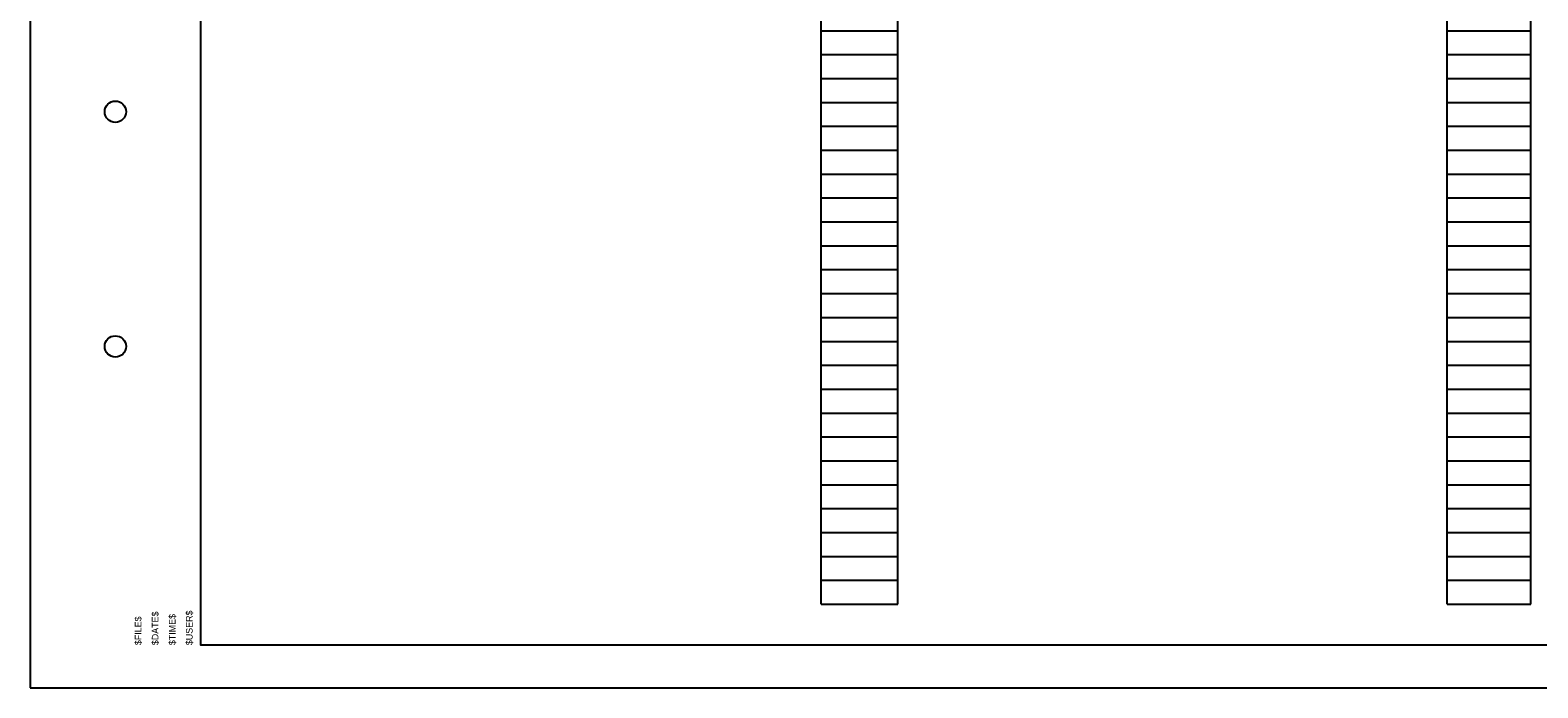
# Model space of a CAD drawing. Extents: x -16 to 102, y -13 to 9.
# Drawn here: x 22.37 to 40.05, y -12.91 to -5.2 of the extents above; entities that cross this region are included whole.
import ezdxf

# ---------------------------------------------------------------- set-up
doc = ezdxf.new("R2010")
doc.units = 0
for name, color, linetype in [('SH_Border', 7, 'Continuous'), ('SH_Cut_Line', 7, 'Continuous'), ('SH_Data', 7, 'Continuous'), ('TX_P_Misc', 7, 'Continuous')]:
    doc.layers.add(name, color=color, linetype=linetype)

msp = doc.modelspace()

# ---------------------------------------------------------------- linework, layer by layer
at = {"layer": 'SH_Border'}
msp.add_lwpolyline([(24.368, 8.593), (55.868, 8.593), (55.868, -12.407), (24.368, -12.407)], close=True, dxfattribs=at)
for centre in [(23.368, -6.157), (23.368, -8.907)]:
    msp.add_circle(centre, 0.125, dxfattribs=at)
at = {"layer": 'SH_Cut_Line'}
msp.add_lwpolyline([(22.368, -12.907), (56.368, -12.907), (56.368, 9.093), (22.368, 9.093)], close=True, dxfattribs=at)
at = {"layer": 'SH_Data'}
for p, q in [((31.642, -11.927), (31.642, 8.233)), ((32.542, -11.927), (32.542, 8.233)), ((38.982, -11.927), (38.982, 8.233)), ((39.962, -11.927), (39.962, 8.233)), ((31.642, -5.207), (32.542, -5.207)), ((38.982, -5.207), (39.962, -5.207)), ((31.642, -5.487), (32.542, -5.487)), ((38.982, -5.487), (39.962, -5.487)), ((31.642, -5.767), (32.542, -5.767)), ((38.982, -5.767), (39.962, -5.767)), ((31.642, -6.047), (32.542, -6.047)), ((38.982, -6.047), (39.962, -6.047)), ((31.642, -6.327), (32.542, -6.327)), ((38.982, -6.327), (39.962, -6.327)), ((31.642, -6.607), (32.542, -6.607)), ((38.982, -6.607), (39.962, -6.607)), ((31.642, -6.887), (32.542, -6.887)), ((38.982, -6.887), (39.962, -6.887)), ((31.642, -7.167), (32.542, -7.167)), ((38.982, -7.167), (39.962, -7.167)), ((31.642, -7.447), (32.542, -7.447)), ((38.982, -7.447), (39.962, -7.447)), ((31.642, -7.727), (32.542, -7.727)), ((38.982, -7.727), (39.962, -7.727)), ((31.642, -8.007), (32.542, -8.007)), ((38.982, -8.007), (39.962, -8.007)), ((31.642, -8.287), (32.542, -8.287)), ((38.982, -8.287), (39.962, -8.287)), ((31.642, -8.567), (32.542, -8.567)), ((38.982, -8.567), (39.962, -8.567)), ((31.642, -8.847), (32.542, -8.847)), ((38.982, -8.847), (39.962, -8.847)), ((31.642, -9.127), (32.542, -9.127)), ((38.982, -9.127), (39.962, -9.127)), ((31.642, -9.407), (32.542, -9.407)), ((38.982, -9.407), (39.962, -9.407)), ((31.642, -9.687), (32.542, -9.687)), ((38.982, -9.687), (39.962, -9.687)), ((31.642, -9.967), (32.542, -9.967)), ((38.982, -9.967), (39.962, -9.967)), ((31.642, -10.247), (32.542, -10.247)), ((38.982, -10.247), (39.962, -10.247)), ((31.642, -10.527), (32.542, -10.527)), ((38.982, -10.527), (39.962, -10.527)), ((31.642, -10.807), (32.542, -10.807)), ((38.982, -10.807), (39.962, -10.807)), ((31.642, -11.087), (32.542, -11.087)), ((38.982, -11.087), (39.962, -11.087)), ((31.642, -11.367), (32.542, -11.367)), ((38.982, -11.367), (39.962, -11.367)), ((31.642, -11.647), (32.542, -11.647)), ((38.982, -11.647), (39.962, -11.647)), ((31.642, -11.927), (32.542, -11.927)), ((38.982, -11.927), (39.962, -11.927)), ((29.642, -12.907), (29.642, -12.907))]:
    msp.add_line(p, q, dxfattribs=at)

# ---------------------------------------------------------------- texts
at = {"layer": 'TX_P_Misc'}
for s, p in [('$DATE$', (23.873, -12.407)), ('$USER$', (24.273, -12.407)), ('$FILE$', (23.673, -12.407)), ('$TIME$', (24.073, -12.407))]:
    msp.add_text(s, height=0.078, rotation=90, dxfattribs=at).set_placement(p)

doc.saveas('drawing.dxf')
